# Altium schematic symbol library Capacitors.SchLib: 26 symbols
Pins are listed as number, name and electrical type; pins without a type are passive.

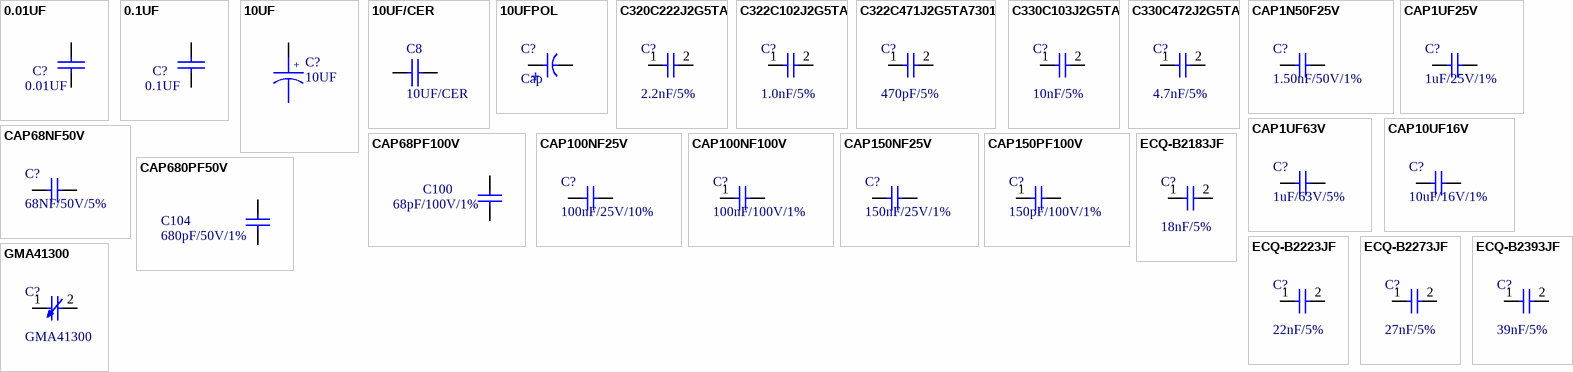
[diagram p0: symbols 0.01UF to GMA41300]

## 0.01UF
designator C?
10000pF ±10% 10V Ceramic Capacitor X7R 0603 (1608 Metric); MFG: Kemet; MFG PN: C0603C103K8RACTU; DK PN: 399-11132-1-ND
footprint 0603
pins: 1, 2

## 0.1UF
designator C?
CAP .10UF 16V CERAMIC X7R 0603; MFG: Kemet; MFG PN: C0603C104K4RACTU; DK PN: 399-1096-1-ND
footprint 0603
pins: 1, 2

## 10UF
designator C?
CAP TANTALUM 10UF 16V 10% SMD; MFG: Kemet; MFG PN: B45196H3106K109; DK PN: 495-2236-1-ND
footprint 1206
pins: 1, 2

## 10UF/CER
designator C8
10µF ±10% 25V Ceramic Capacitor X7S 0805; Text Field1: Murata; Text Field2: GRM21BC71E106KE11L; Text Field3: 490-10496-1-ND
footprint 0805
pins: 1, 2

## 10UFPOL
designator C?, comment Cap
10µF 25V Aluminum Electrolytic Capacitors Radial, Can - SMD 5000 Hrs @ 105°C; MFG PN: UUL1E100MCL1GS; DK PN: 493-9511-1-ND
footprint ECAP5X5.8
pins: 1, 2

## C320C222J2G5TA
designator C?, comment 2.2nF/5%
2200pF ±5% 200V Ceramic Capacitor C0G, NP0 Radial; MFG PN: C320C222J2G5TA; DK PN: 399-4282-ND; MFG: Kemet
footprint Model Name (Footprint not found)
footprint C32X
pins: 1, 2
1 alternate drawing of the same symbol

## C322C102J2G5TA
designator C?, comment 1.0nF/5%
1000pF ±5% 200V Ceramic Capacitor C0G, NP0 Radial; MFG PN: C322C102J2G5TA; DK PN: 399-4322-ND; MFG: Kemet
footprint Model Name (Footprint not found)
footprint C32X
pins: 1, 2
1 alternate drawing of the same symbol

## C322C471J2G5TA7301
designator C?, comment 470pF/5%
470pF ±5% 200V Ceramic Capacitor C0G, NP0 Radial; MFG PN: C322C471J2G5TA7301; DK PN: 399-14100-2-ND; MFG: Kemet
footprint Model Name (Footprint not found)
footprint C32X
pins: 1, 2
1 alternate drawing of the same symbol

## C330C103J2G5TA
designator C?, comment 10nF/5%
10000pF ±5% 200V Ceramic Capacitor C0G, NP0 Radial; MFG PN: C330C103J2G5TA; DK PN: 399-4385-ND; MFG: Kemet
footprint Model Name (Footprint not found)
footprint C330
pins: 1, 2
1 alternate drawing of the same symbol

## C330C472J2G5TA
designator C?, comment 4.7nF/5%
4700pF ±5% 200V Ceramic Capacitor C0G, NP0 Radial; MFG PN: C330C472J2G5TA; DK PN: 399-4412-ND; MFG: Kemet
footprint Model Name (Footprint not found)
footprint C330
pins: 1, 2
1 alternate drawing of the same symbol

## CAP1N50F25V
designator C?, comment 1.50nF/50V/1%
CAP CER 1500PF 50V C0G/NP0 0603; MFG PN: C0603C152F5GACTU; DK PN: 399-11139-6-ND; MFG: Kemet
footprint MY0603
pins: 1, 2

## CAP1UF25V
designator C?, comment 1uF/25V/1%
1µF ±10% 25V Ceramic Capacitor X7R 0603 (1608 Metric); MFG PN: 06033C105KAT2A; DK PN: 478-10046-1-ND; MFG: AVX
footprint MY0603
pins: 1, 2

## CAP1UF63V
designator C?, comment 1uF/63V/5%
CAP FILM 1UF 5% 63VDC RADIAL; MFG PN: R82DC4100AA60J; DK PN: 399-5860-ND; MFG: Kemet
footprint CAP5MM
pins: 1, 2

## CAP10UF16V
designator C?, comment 10uF/16V/1%
10µF ±10% 16V Ceramic Capacitor X7R 0805 (2012 Metric); MFG PN: CL21B106KOQNNNE; DK PN: 1276-2872-1-ND; MFG: Samsung
footprint MY0805
pins: 1, 2

## CAP68NF50V
designator C?, comment 68NF/50V/5%
0.068µF ±5% 50V Ceramic Capacitor C0G, NP0 1206 (3216 Metric); MFG PN: GRM31C5C1H683JA01L; DK PN: 490-3360-1-ND; MFG: Murate
footprint MY1206
pins: 1, 2

## CAP68PF100V
designator C100, comment 68pF/100V/1%
68pF ±1% 100V Ceramic Capacitor C0G, NP0 0805 (2012 Metric); MFG PN: 08051A680FAT2A; DK PN: 478-10409-1-ND; MFG: Samsung
footprint MY0805
pins: 1, 2

## CAP100NF25V
designator C?, comment 100nF/25V/10%
0.1µF ±10% 25V Ceramic Capacitor X7R 0603 (1608 Metric); MFG PN: 06033C104KAT2A; DK PN: 478-3714-1-ND; MFG: AVX
footprint MY0603
pins: 1, 2

## CAP100NF100V
designator C?, comment 100nF/100V/1%
0.1µF ±5% 100V Ceramic Capacitor C0G, NP0 1206 (3216 Metric); MFG PN: CGA5L1C0G2A104J160AC; DK PN: 445-172694-1-ND; MFG: TDK
footprint MY1206
pins: 1, 2

## CAP150NF25V
designator C?, comment 150nF/25V/1%
0.15µF ±5% 25V Ceramic Capacitor X7R 0805 (2012 Metric); MFG PN: 08053C154JAT2A; DK PN: 478-10488-2-ND; MFG: AVX
footprint MY0805
pins: 1, 2

## CAP150PF100V
designator C?, comment 150pF/100V/1%
150pF 100V Ceramic Capacitor C0G, NP0 1206 (3216 Metric) 0.126" L x 0.063" W (3.20mm x 1.60mm); MFG PN: 12061A151JAT2A; DK PN: 478-1445-1-ND; MFG: AVX
footprint MY1206
pins: 1, 2

## CAP680PF50V
designator C104, comment 680pF/50V/1%
680pF ±1% 50V Ceramic Capacitor C0G, NP0 0603 (1608 Metric); MFG PN: C0603C681F5GACTU; DK PN: 399-7948-1-ND; MFG: Kemet
footprint MY0603
pins: 1, 2

## ECQ-B2183JF
designator C?, comment 18nF/5%
0.018µF Film Capacitor 200V Polyester Radial; MFG PN: ECQ-B2183JF; DK PN: P4552A-ND; MFG: Panasonic
footprint Model Name (Footprint not found)
footprint ECQ-B2273JF
pins: 1, 2
1 alternate drawing of the same symbol

## ECQ-B2223JF
designator C?, comment 22nF/5%
0.022µF Film Capacitor 200V Polyester Radial; MFG PN: ECQ-B2223JF; DK PN: P4553A-ND; MFG: Panasonic
footprint Model Name (Footprint not found)
footprint ECQ-B2273JF
pins: 1, 2
1 alternate drawing of the same symbol

## ECQ-B2273JF
designator C?, comment 27nF/5%
0.027µF Film Capacitor 200V Polyester Radial; MFG PN: ECQ-B2273JF; DK PN: P4554A-ND; MFG: Panasonic
footprint Model Name (Footprint not found)
footprint ECQ-B2273JF
pins: 1, 2
1 alternate drawing of the same symbol

## ECQ-B2393JF
designator C?, comment 39nF/5%
0.039µF Film Capacitor 200V Polyester Radial; MFG PN: ECQ-B2393JF; DK PN: P4556A-ND; MFG: Panasonic
footprint Model Name (Footprint not found)
footprint ECQ-B2393JF
pins: 1, 2
1 alternate drawing of the same symbol

## GMA41300
designator C?
360 ~ 1200pF Trimmer Capacitor 175V Top Bracket Mount; DK PN: SG9218-ND; MFG: Sprague
footprint Model Name (Footprint not found)
footprint GMA4
pins: 1, 2
1 alternate drawing of the same symbol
